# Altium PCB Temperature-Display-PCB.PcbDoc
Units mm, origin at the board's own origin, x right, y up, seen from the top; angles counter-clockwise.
Board outline 37.1 x 26.3 mm, 2 copper layers (Top Layer, Bottom Layer); 8 components, 9 nets, 61 pads, 8 vias.
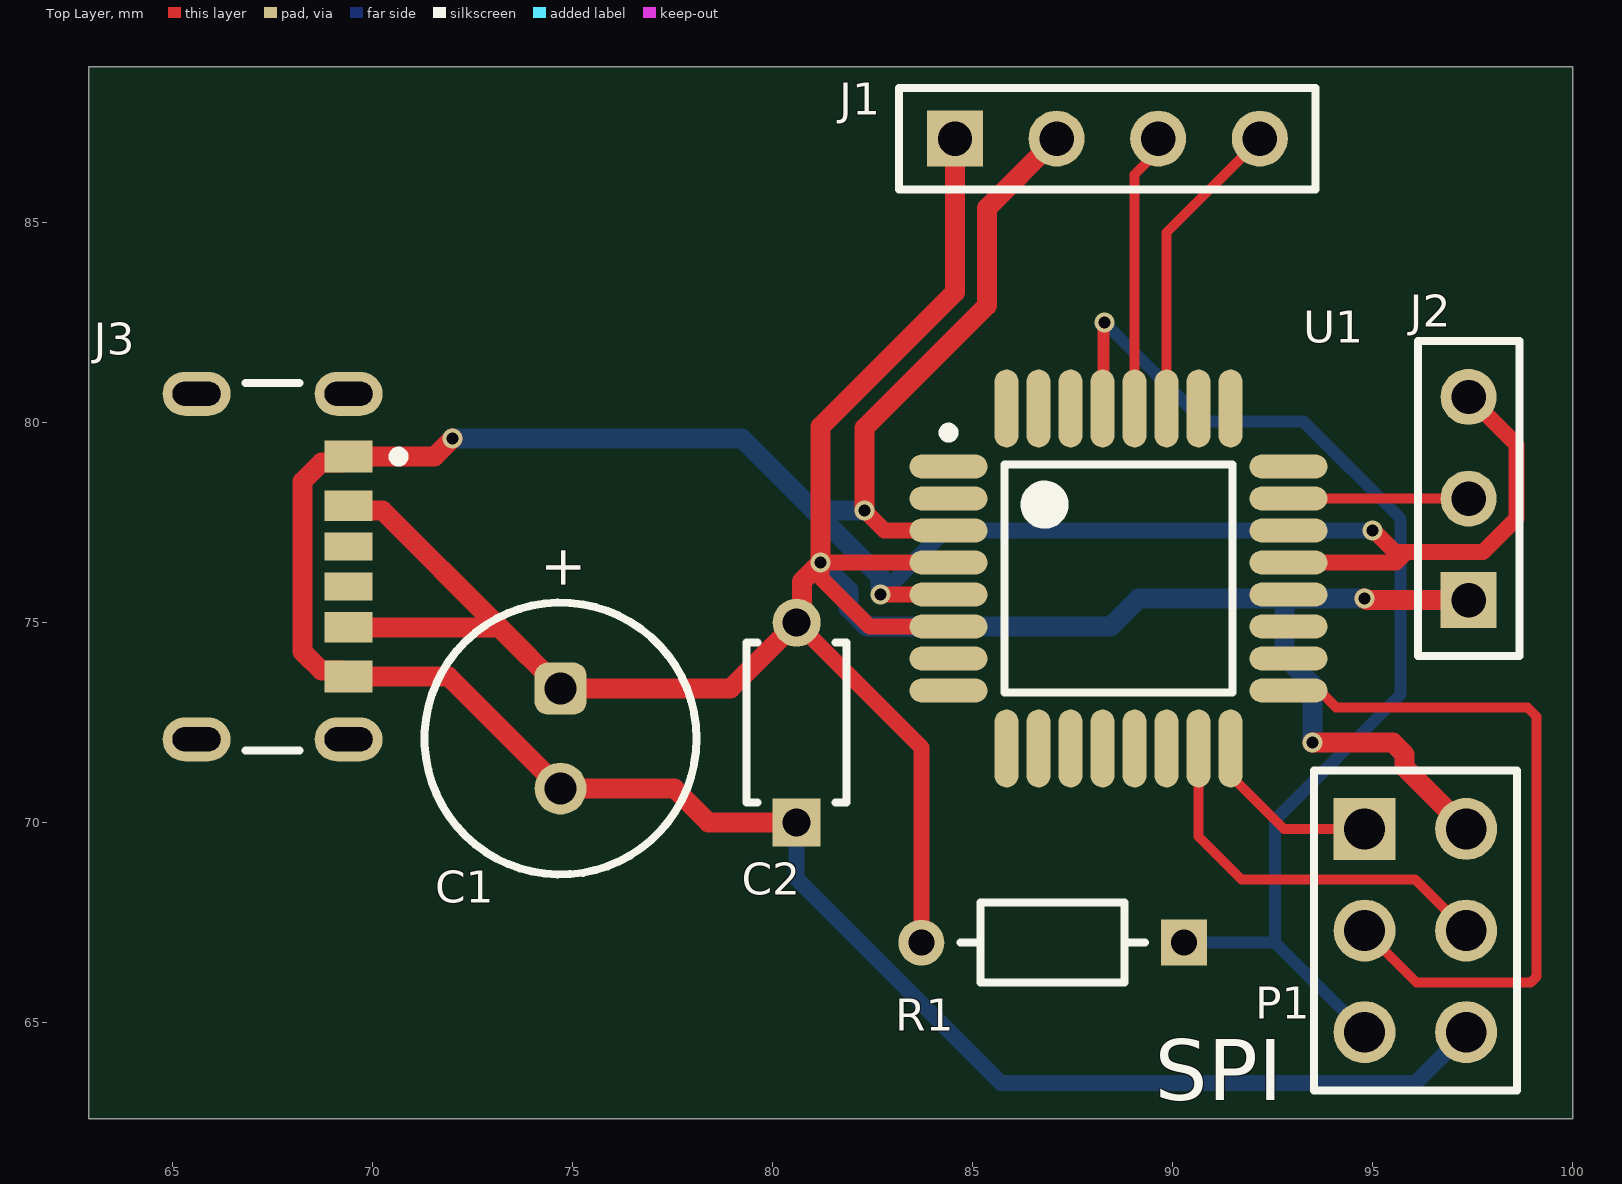
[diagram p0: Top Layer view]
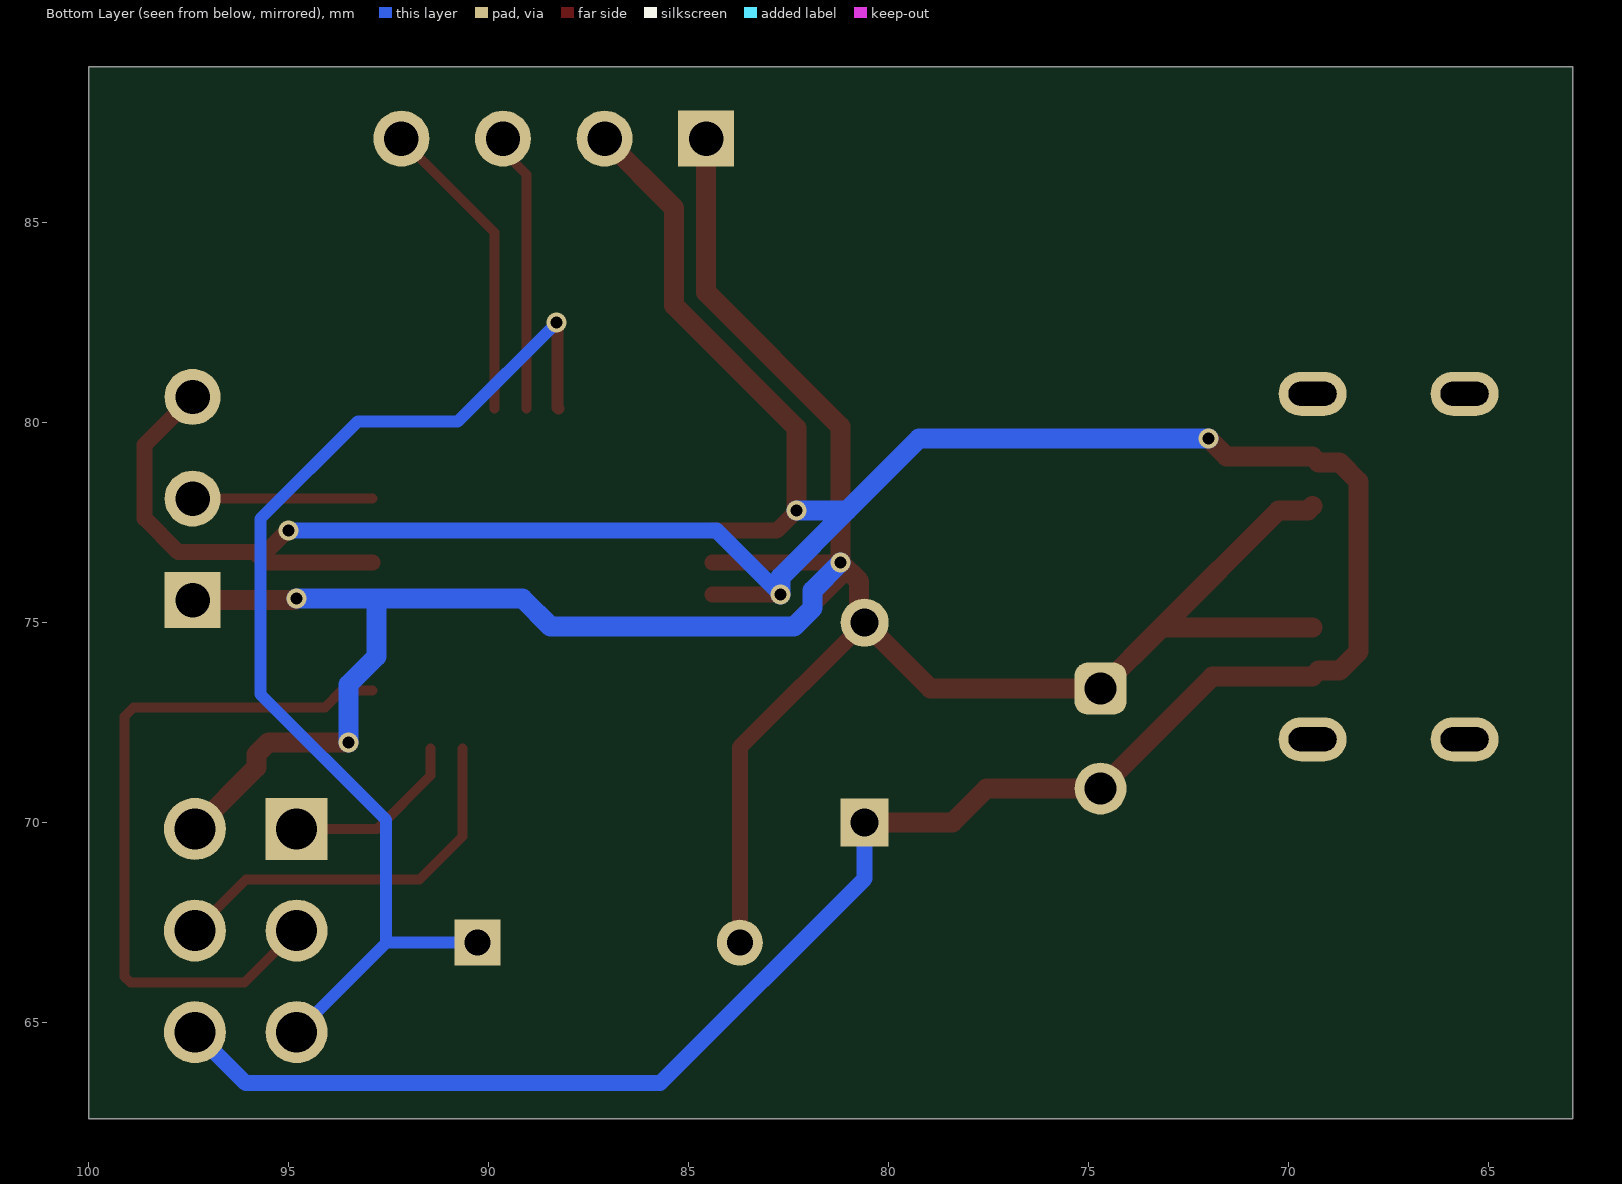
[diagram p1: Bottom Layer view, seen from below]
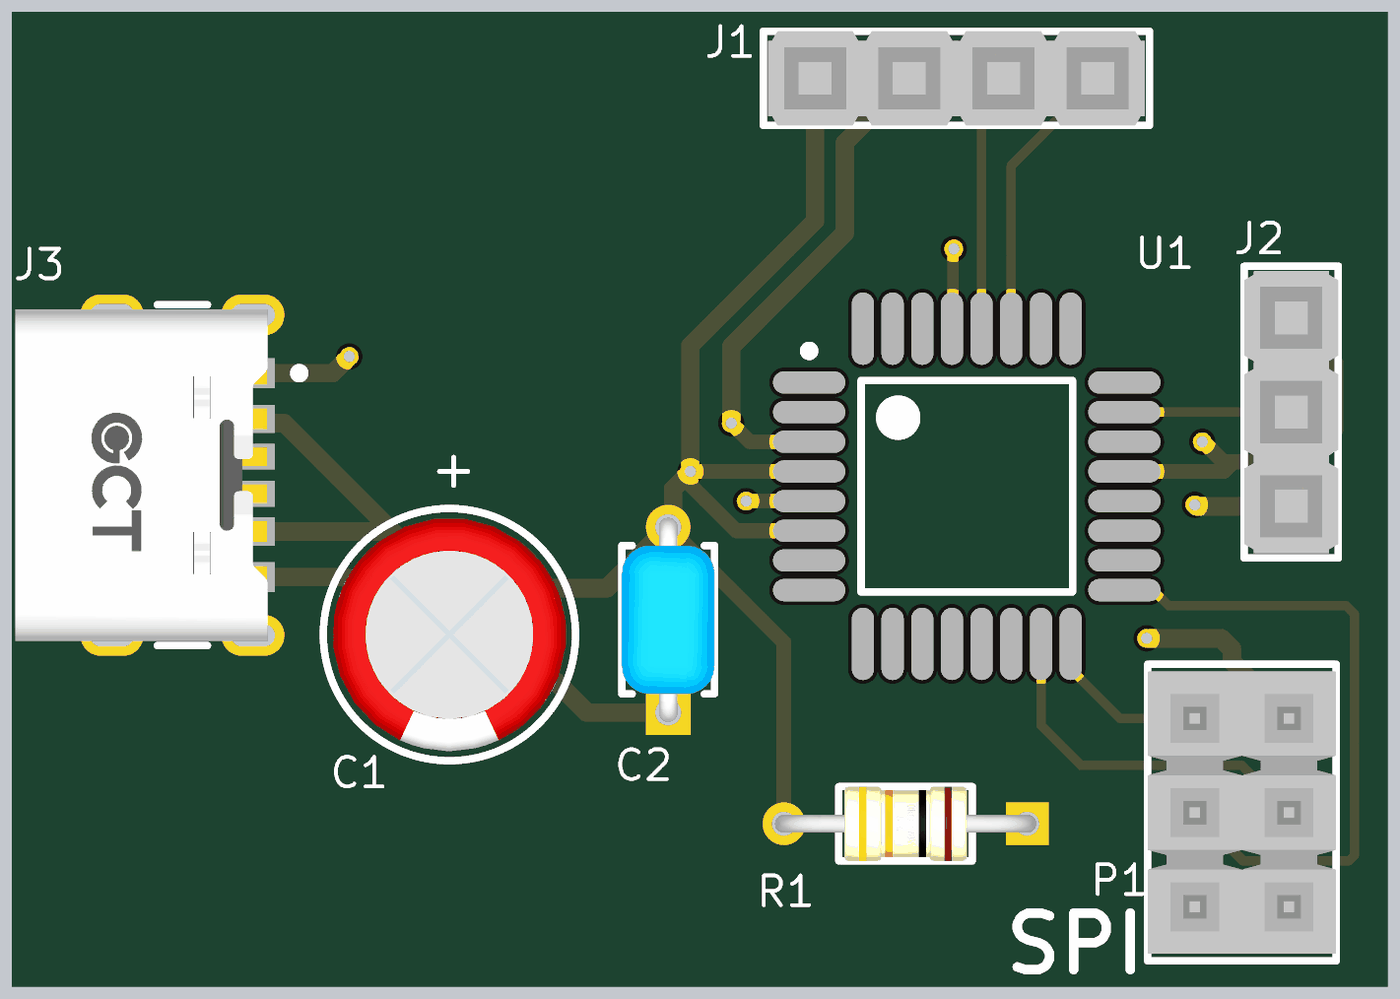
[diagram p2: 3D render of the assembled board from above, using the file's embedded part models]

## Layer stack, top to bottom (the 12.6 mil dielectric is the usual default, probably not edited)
Top Solder: solder mask 0.0102, Solder Resist, Dk 3.5
Top Layer: signal copper 0.0356
Dielectric 1: dielectric 0.32, FR-4, Dk 4.8
Bottom Layer: signal copper 0.0356
Bottom Solder: solder mask 0.0102, Solder Resist, Dk 3.5

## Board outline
62.9,62.6 62.9,88.9 100,88.9 100,62.6

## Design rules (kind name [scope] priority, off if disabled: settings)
Clearance [All] p1: gap=0.1 ignorepadtopadclearanceinfootprint=FALSE except(0.3: Arc-Arc Arc-Track Arc-SMDPad Arc-THPad Arc-Via Arc-Hole Track-Track Track-SMDPad Track-THPad Track-Via Track-Hole)
PolygonConnect [All] p1: connectstyle=Relief reliefconductorwidth=0.254 reliefentries=4 polygonreliefangle="90 Angle" airgapwidth=0.254
RoutingVias [All] p1: holewidth=0.305 width=0.508 viastyle="Through Hole" minholewidth=0.305 minwidth=0.508 maxholewidth=0.305 maxwidth=0.508
SolderMaskExpansion [All] p1: expansion=0.102 istentingtop=FALSE
SupplyNets "Schematic Supply Nets_1" [InNet('GND')] p1: voltage=0.000
SupplyNets "Schematic Supply Nets" [InNet('VCC')] p2: voltage=0.000
Width "GND Width" [InNet('GND')] p1: maxlimit=1 minlimit=0.4 preferedwidth=0.5
Width "VCC Width" [InNet('VCC')] p2: maxlimit=1 minlimit=0.4 preferedwidth=0.5
Width "Signal Width" [All] p3: maxlimit=0.3 minlimit=0.15 preferedwidth=0.25
30 further rules are at their usual default settings.

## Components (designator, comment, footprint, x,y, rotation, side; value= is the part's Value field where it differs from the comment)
C1 "860130573001" WCAP-ATET_D6.3H11 74.7,72.1 r90 top value=22µF
C2 "RCER72A104K1M1H03A" FP-RCE1K1-2_5-MFG 80.6,72.5 r90 top value=100nF
J1 "SLW-104-01-F-S" SMTC-SLW-104-01-X-S 84.56,87.1 r0 top
J2 "SLW-103-01-L-S" SMTC-SLW-103-01-X-S 97.4,75.56 r90 top
J3 "USB4125-GF-A-0190" FP-USB4125-GF-A-0190-MFG 66.4,76.4 r270 top
P1 "TSW-103-08-F-D" SMTC-TSW-103-08-X-D 94.8,69.84 r270 top
R1 "CF18JT10K0" FP-CF18-MFG 87,67 r180 top value=10kΩ
U1 "ATmega328P-AU" 32A_M 88.65,76.1 r0 top

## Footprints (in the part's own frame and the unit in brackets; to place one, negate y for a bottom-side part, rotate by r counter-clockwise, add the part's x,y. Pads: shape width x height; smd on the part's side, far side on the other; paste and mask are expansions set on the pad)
32A_M [mm] "Thin QFP, 32-Leads, Body 7x7mm, Pitch 0.8mm, IPC Low Density"
  oval 1.95x0.6 smd: 1(-4.25,2.8) 2(-4.25,2) 3(-4.25,1.2) 4(-4.25,0.4) 5(-4.25,-0.4) 6(-4.25,-1.2) 7(-4.25,-2) 8(-4.25,-2.8) 17(4.25,-2.8) 18(4.25,-2) 19(4.25,-1.2) 20(4.25,-0.4) 21(4.25,0.4) 22(4.25,1.2) 23(4.25,2) 24(4.25,2.8)
  oval 0.6x1.95 smd: 9(-2.8,-4.25) 10(-2,-4.25) 11(-1.2,-4.25) 12(-0.4,-4.25) 13(0.4,-4.25) 14(1.2,-4.25) 15(2,-4.25) 16(2.8,-4.25) 25(2.8,4.25) 26(2,4.25) 27(1.2,4.25) 28(0.4,4.25) 29(-0.4,4.25) 30(-1.2,4.25) 31(-2,4.25) 32(-2.8,4.25)
  silkscreen extent -4.37,-2.85 2.85,3.77, body extent -3.5,-3.5 3.5,3.5, height 1.2
FP-CF18-MFG [mm]
  rect 1.15x1.15 hole 0.65 paste-2539.97 mask+0: 1(-3.28,0)
  round 1.15 hole 0.65 paste-2539.97 mask+0: 2(3.28,0)
  silkscreen extent -2.3,-1 2.3,1, body extent -3.96,-1.1 3.96,1.1, height 0.25
FP-RCE1K1-2_5-MFG [mm]
  rect 1.2x1.2 hole 0.7 paste-2539.97 mask+0: 1(-2.5,0)
  round 1.2 hole 0.7 paste-2539.97 mask+0: 2(2.5,0)
  silkscreen extent -2,-1.25 2,1.25, body extent -2.75,-1.25 2.75,1.25, height 5
FP-USB4125-GF-A-0190-MFG [mm]
  rrect100% 1.1x1.7 hole 1.2 slot 0.6 at 0 deg paste-2539.97 mask+0: 1(-4.32,3) 2(4.32,3) 3(-4.32,-0.8) 4(4.32,-0.8)
  rect 0.7x1.2 smd paste+0 mask+0: A5(-0.5,3) B5(0.5,3)
  rect 0.76x1.2 smd paste+0 mask+0: A9(1.52,3) B9(-1.52,3)
  rect 0.8x1.2 smd paste+0 mask+0: A12(2.75,3) B12(-2.75,3)
  silkscreen extent -4.59,0.43 4.59,4.38, body extent -4.97,-3.57 4.97,3.95, height 0.25
SMTC-SLW-103-01-X-S [mm] "Low Profile Socket Strip, 1x3 Pins, Vertical, 2.54mm Pitch, Female"
  rect 1.4x1.4 hole 0.86: 1(0,0)
  round 1.4 hole 0.86: 2(2.54,0) 3(5.08,0)
  silkscreen extent -1.4,-1.27 6.48,1.27, body extent -1.27,-1.27 6.35,1.27, height 4.57
SMTC-SLW-104-01-X-S [mm] "Low Profile Socket Strip, 1x4 Pins, Vertical, 2.54mm Pitch, Female"
  rect 1.4x1.4 hole 0.86: 1(0,0)
  round 1.4 hole 0.86: 2(2.54,0) 3(5.08,0) 4(7.62,0)
  silkscreen extent -1.4,-1.27 9.02,1.27, body extent -1.27,-1.27 8.89,1.27, height 4.57
SMTC-TSW-103-08-X-D [mm] ".025 SQ Post Terminal Strip Assembly, 2x3 Pins, Vertical, 2.54mm Pitch, Male"
  rect 1.55x1.55 hole 1.02: 1(0,0)
  round 1.55 hole 1.02: 2(0,2.54) 3(2.54,0) 4(2.54,2.54) 5(5.08,0) 6(5.08,2.54)
  silkscreen extent -1.46,-1.27 6.54,3.81, body extent -1.27,-1.27 6.35,3.81, height 8.38
WCAP-ATET_D6.3H11 [mm] "Aluminum Electrolytic Capacitors, 6.3x11mm"
  rrect50% 1.3x1.3 hole 0.8: 1(1.25,0)
  round 1.3 hole 0.8: 2(-1.25,0)
  silkscreen extent -3.4,-3.4 3.4,3.4, body extent -3.14,-3.15 3.14,3.14, height 11.26

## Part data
C1: library part CMP-03913-54218083-2, "WCAP-ATET Aluminum Electrolytic Capacitors", Capacitance=22µF, Case/Package=Radial, Leakage Current=7.7µA, Max Operating Temperature=125°C, Min Operating Temperature=-40°C, Ripple Current=82mA, Tolerance=20%, Voltage Rating=35V
C2: library part CMP-06035-028865-1, "Cap Ceramic Monolithic 100nF 100V 10% Thru-Hole Bulk", Capacitance=100nF, Case/Package=Radial, Dielectric=X7R, Max Operating Temperature=125°C, Min Operating Temperature=-55°C, Package Quantity=2000, Ratings=AEC-Q200, Resistor Type=Ceramic, Tolerance=10%, Voltage Rating=100V
J1: library part CMP-1023-00132-1, "Low Profile Socket Strips, Through-hole, Vertical, -55 to 125 degC, 2.54 mm Pitch, 4-Pin, Female, RoHS", Manufacturer=Samtec, Temperature Range="-55 to 125 degC"
J2: library part CMP-1023-00127-1, "Low Profile Socket Strips, Through-hole, Vertical, -55 to 125 degC, 2.54 mm Pitch, 3-Pin, Female, RoHS", Manufacturer=Samtec, Temperature Range="-55 to 125 degC"
J3: library part CMP-245163-000004-1, "CONN RCPT TYPE C 6P SMD RA"
P1: library part CMP-1024-00337-1, "0.025\" SQ Post Header, Through-hole, Vertical, -55 to 125 degC, 2.54 mm Pitch, 6-Pin, Male, RoHS", Manufacturer=Samtec, Temperature Range="-55 to 125 degC"
R1: library part CMP-26528-000002-1, "RES 10K OHM 1/8W 5% CF AXIAL", Manufacturer="Stackpole Electronics", Package=CF18, Power Rating=0.125W, Resistance=10kΩ, Temperature="-55°C to +155°C", Temperature Coefficient=0-500ppm/°C, Temperature Range High=+155°C, Temperature Range Low=-55°C, Tolerance=5%, Voltage Rating=250V
U1: library part CMP-0095-00269-2, "8-bit AVR Microcontroller, 32KB Flash, 1KB EEPROM, 2KB SRAM, 32-pin TQFP, Industrial Grade (-40°C to 85°C)"

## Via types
v1: diameter 0.508, hole 0.305, Top Layer to Bottom Layer, 8 vias

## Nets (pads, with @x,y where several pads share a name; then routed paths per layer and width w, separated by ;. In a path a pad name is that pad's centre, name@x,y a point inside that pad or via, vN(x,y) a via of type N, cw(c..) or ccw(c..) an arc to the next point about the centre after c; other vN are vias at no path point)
GND: C1.2 C2.1 J1.2 J2.3 J3.A12 J3.B12 P1.6 U1.3 U1.5 U1.21 | length 96.2
  Top Layer w0.4: v1(82.3,77.8) 82.8,77.3 U1.3 ; v1(82.7,75.7) U1.5 ; U1.21 95.582,76.5 95.842,76.76 ; v1(95,77.3) 95.029,77.3 95.569,76.76 95.842,76.76 ; J2.3 98.6,79.44 98.6,77.603 97.757,76.76 95.842,76.76
  Top Layer w0.5: v1(72,79.6) 71.55,79.15 J3.B12 69.25,79 68.722,79 68.25,78.528 68.25,74.272 68.722,73.8 69.25,73.8 J3.A12 71.9,73.65 C1.2 77.55,70.85 78.4,70 C2.1 ; v1(82.3,77.8) 82.3,79.865 85.36,82.925 85.36,85.36 J1.2
  Bottom Layer w0.4: C2.1 80.6,68.6 85.715,63.485 96.065,63.485 P1.6 ; v1(82.7,75.7) 84.3,77.3 v1(95,77.3)
  Bottom Layer w0.5: v1(72,79.6) 79.237,79.6 81.037,77.8 ; v1(82.3,77.8) 81.037,77.8 ; v1(82.7,75.7) 82.698,75.702 82.698,76.139 81.037,77.8
MISO: P1.1 U1.16 | length 4.6
  Top Layer w0.25: U1.16 91.45,71.175 92.785,69.84 P1.1
MOSI: P1.4 U1.15 | length 9.9
  Top Layer w0.25: U1.15 90.65,69.65 91.726,68.574 96.066,68.574 P1.4
RESET: P1.5 R1.1 U1.29 | length 28.9
  Top Layer w0.3: U1.29 88.275,80.375 88.275,82.475 v1(88.3,82.5)
  Bottom Layer w0.3: v1(88.3,82.5) 90.774,80.026 93.27,80.026 95.704,77.592 95.704,73.208 92.56,70.064 92.56,67 ; R1.1 92.56,67 ; P1.5 92.56,67
SCK: P1.3 U1.17 | length 17.9
  Top Layer w0.25: U1.17 93.67,73.3 94.09,72.879 98.874,72.879 99.1,72.654 99.1,66.146 98.954,66 96.1,66 P1.3
SCL: J1.3 U1.28 | length 7
  Top Layer w0.25: U1.28 89.05,86.199 89.64,86.789 J1.3
SDA: J1.4 U1.27 | length 7.7
  Top Layer w0.25: U1.27 89.85,84.75 92.18,87.08 J1.4
TEMP_DATA: J2.2 U1.23 | length 4.5
  Top Layer w0.25: U1.23 J2.2
VCC: C1.1 C2.2 J1.1 J2.1 J3.A9 J3.B9 P1.2 R1.2 U1.4 U1.6 | length 74.1
  Top Layer w0.4: C2.2 83.72,71.88 R1.2 ; U1.6 82.434,74.9 81.221,76.113 81.221,76.479 v1(81.2,76.5) U1.4
  Top Layer w0.5: J3.A9 73.17,74.88 ; J3.B9 69.52,77.8 70.25,77.8 73.17,74.88 ; J1.1 84.56,83.256 81.2,79.896 v1(81.2,76.5) 81.2,76.498 80.734,76.032 80.734,75.134 C2.2 78.95,73.35 C1.1 73.17,74.88 ; v1(93.5,72) 95.507,72 95.8,71.707 95.8,71.38 P1.2 ; v1(94.8,75.6) 94.802,75.6 94.842,75.56 J2.1
  Bottom Layer w0.5: v1(81.2,76.5) 81.896,75.804 81.896,75.367 82.367,74.896 82.804,74.896 88.449,74.896 89.153,75.6 92.8,75.6 ; v1(93.5,72) 93.5,73.451 92.8,74.151 92.8,75.6 ; v1(94.8,75.6) 92.8,75.6
pads on no net: J3.1 J3.2 J3.3 J3.4 J3.A5 J3.B5 U1.1 U1.2 U1.7 U1.8 U1.9 U1.10 U1.11 U1.12 U1.13 U1.14 U1.18 U1.19 U1.20 U1.22 U1.24 U1.25 U1.26 U1.30 U1.31 U1.32

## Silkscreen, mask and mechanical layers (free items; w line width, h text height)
Top Overlay:
  text "SPI" at 89.554,63.054 h1.52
